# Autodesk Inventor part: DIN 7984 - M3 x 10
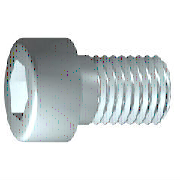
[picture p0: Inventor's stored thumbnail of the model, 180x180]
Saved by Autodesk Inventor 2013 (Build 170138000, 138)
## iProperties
Created: 2012-02
Part Number: DIN 7984 - M3 x 10
Material: Stahl, weich
Description: Zylinderkopfschraube
Document SubType Name: Modeling
Standard: DIN 7984
Designer: SteffenHaase
Standard Revision: 1985
Standards Organization: DIN
Language: de-DE
Size Designation: M3 x 10
Categories: <MemberInstance><Categories><Category DisplayName="Verbindungselemente" InternalName="e4da775c-781d-43d5-af7c-5136215cf5a6" Mnemonic="FSTN"><Category DisplayNam
Density: 1 g/cm^3
IsCustomPart: 0
Author: SteffenHaase
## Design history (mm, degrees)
sketch "Skizze1"
  geometry: L1 (0.167, 0)-(10, 0); L2 (10, 0)-(10, 1.5); L3 (10, 1.5)-(1.5, 1.5); L4 (1.5, 1.5)-(1.193, 1.5); L5 (1.193, 1.5)-(0, 1.5); L6 (0, 1.5)-(0, 2.75); L7 (0, 2.75)-(-2, 2.75); L8 (-2, 2.75)-(-2, 1.155); L9 (-2, 1.155)-(-0.5, 1.155); L10 (-0.5, 1.155)-(0.167, 0); L11 (-4.4, 0)-(12.4, 0) reference; L12 (0, -0.55)-(0, 3.3) reference; L13 (1.5, 1.5)-(0, 1.5)
  constraints: 22 end point, 6 parallel, 2 collinear, 2 perpendicular, 1 horizontal, 1 point on line
  dimensions: "d1" = 8.5 distance from line of L3.end L2 (= GEL); "d2" = 0.30683 distance of L4.end L3.end (computed from GAL); "d3" = 2 distance between parallel lines of L8 L6 (= KOH); "d4" = 1.5 distance of L8.end L9.end (= INTI); "d5" = 60 deg angle of L10 L1; "d6" = 3 diameter of L3 L1 (= GD); "d7" = 3 diameter of L5 L1 (= BDM); "d8" = 2.3094 diameter of L9 L1 (= 1.1547 x SW); "d9" = 5.5 diameter of L7 L1 (= KOD); "d26" = 10 distance between parallel lines of L12 L2 (= NLG)
revolve "Körper" sketch "Skizze1" stored, may be unused: angle "d10" = 90 deg
sketch "Skizze2"
  geometry: L1 (0, -3.85)-(0, 3.85) reference; L2 (-3.85, 0)-(3.85, 0) reference; L3 (1.155, 0)-(0.577, -1); L4 (0.577, -1)-(-0.577, -1); L5 (-0.577, -1)-(-1.155, 0); L6 (-1.155, 0)-(-0.577, 1); L7 (-0.577, 1)-(0.577, 1); L8 (0.577, 1)-(1.155, 0); 2 further points
  constraints: 12 end point, 1 coincident, 1 horizontal alignment, 1 point on line, 12 other
extrude "Loch" join sketch "Skizze2" stored distance "d11" = 10; taper "d12" = 0 deg
workplane "Work Plane1"
fillet "Fillet2" dims "d30" = 0.1 (= R)
body "Solid1"
fillet "Rundung1" dims "d17" = 0.3 (= RR)
feature "Gewinde" dims "d13" = 8.5 (= GEL), "d14" = 0
chamfer "Fase1" distance "d15" = 0.30673 (= -0.5 x SPD + 0.5 x GD); stored, may be unused: second distance "d16" = 0.30673 (= GUL), angle "d27" = 45 deg
other parameters: "GD" = 3 (= NND) [user parameter; used in 2 equation terms], "NLG" = 10 [user parameter; used in 1 equation term], "GEL" = 8.5 [user parameter; used in 2 equation terms], "KOD" = 5.5 [user parameter; used in 1 equation term], "KOH" = 2 [user parameter; used in 1 equation term], "INTI" = 1.5 [user parameter; used in 1 equation term], "GAL" = 0.30673 (= 0.61345 x PTC) [user parameter; used in 1 equation term], "GUL" = 0.30673 (= 0.61345 x PTC) [user parameter; used in 1 equation term], "BDM" = 3 (= NND) [user parameter; used in 1 equation term], "SW" = 2 [user parameter; used in 2 equation terms], "RR" = 0.3 [user parameter; used in 1 equation term], "SPD" = 2.38655 (= NND - 1.2269 x PTC) [user parameter; used in 1 equation term], "d19" = 0, "d28" = 0, "d29" = 0, "R" = 0.1 [user parameter; used in 1 equation term], "TOA" = 30 deg [user parameter], "GD1" = 2.38655 (= THREADDIA - 1.2269 x PTC) [user parameter], "THREADDIA" = 3 [user parameter; used in 1 equation term], "FAWI" = 45 deg [user parameter], "ANG" = 120 deg [user parameter], "PTC" = 0.5 [user parameter; used in 5 equation terms], "NND" = 3 [user parameter; used in 3 equation terms], "E0" = 2.31 (= 1.155 x SW) [user parameter]
